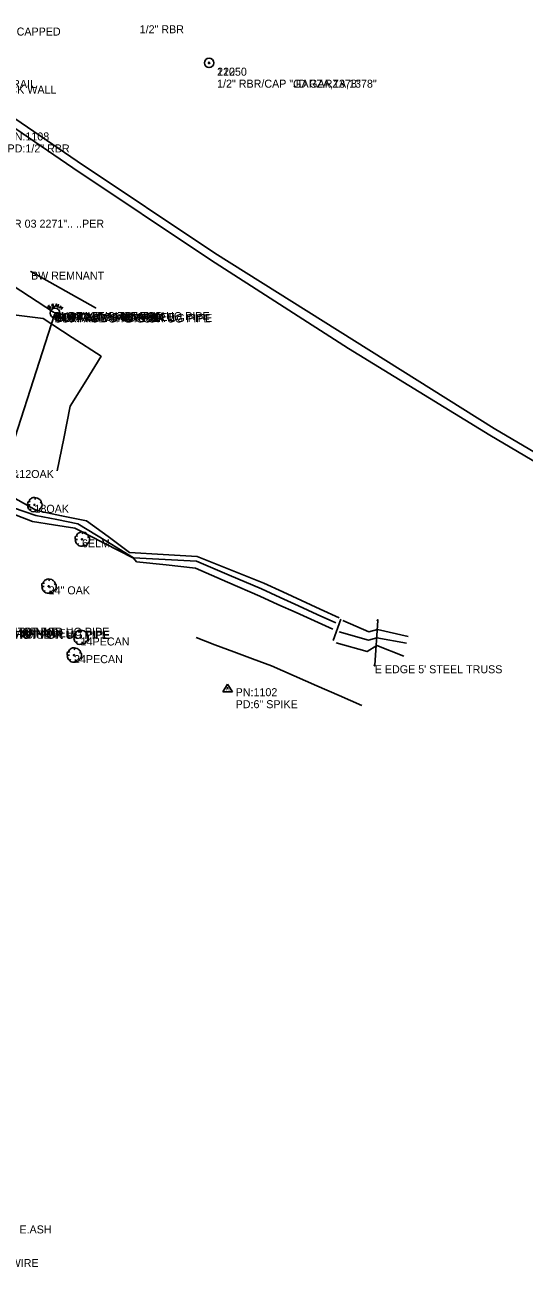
# Model space of a CAD drawing. Extents: x 997398 to 1003416, y 334596 to 337085.
# Drawn here: x 999504 to 999815, y 335282 to 336058 of the extents above; entities that cross this region are included whole.
import ezdxf

# ---------------------------------------------------------------- set-up
doc = ezdxf.new("R2010")
doc.units = 0
for name, color, linetype in [('S_BRIDGE', 7, 'Continuous'), ('S_BRIDGE_ANNOT', 7, 'Continuous'), ('S_EDGE_CONCRETE', 7, 'Continuous'), ('S_ELECTRIC_UTILITIES_ANNOT', 7, 'Continuous'), ('S_FENCE', 7, 'Continuous'), ('S_FENCE_ANNOT', 7, 'Continuous'), ('S_FIBER_OPTIC_CABLE_ANNOT', 7, 'Continuous'), ('S_GAS_UTILITIES_ANNOT', 7, 'Continuous'), ('S_GRD_PT_SYM', 7, 'Continuous'), ('S_IRON_PIN', 7, 'Continuous'), ('S_IRON_PIN_ANNOT', 7, 'Continuous'), ('S_MANHOLE_ANNOT', 7, 'Continuous'), ('S_MISC_TOPO_POINT', 7, 'Continuous'), ('S_MSC_PT_SYM', 7, 'Continuous'), ('S_RAILROAD', 7, 'Continuous'), ('S_RAILROAD_ANNOT', 7, 'Continuous'), ('S_SANITARY_SEWER', 7, 'Continuous'), ('S_SANITARY_SEWER_ANNOT', 7, 'Continuous'), ('S_SECONDARY_CTL', 7, 'Continuous'), ('S_SECONDARY_CTL_ANNOT', 7, 'Continuous'), ('S_STR_PT_SYM', 7, 'Continuous'), ('S_STREAM', 7, 'Continuous'), ('S_SURVEY_TEXT_ANNOT', 7, 'Continuous'), ('S_TREE', 7, 'Continuous'), ('S_TREE_ANNOT', 7, 'Continuous'), ('S_UTL_PT_SYM', 7, 'Continuous')]:
    doc.layers.add(name, color=color, linetype=linetype)

msp = doc.modelspace()

# ---------------------------------------------------------------- linework, layer by layer
at = {"layer": 'S_BRIDGE'}
msp.add_line((999721.99, 335657.91), (999723.92, 335685.93), dxfattribs=at)
at = {"layer": 'S_EDGE_CONCRETE'}
msp.add_lwpolyline([(999700.78, 335686.72), (999696, 335673.33)], dxfattribs=at)
at = {"layer": 'S_FENCE'}
msp.add_line((999507.42, 335903.8), (999547.73, 335881.19), dxfattribs=at)
at = {"layer": 'S_GRD_PT_SYM'}
for points in [[(999521.53, 335878.51), (999521.53, 335878.56), (999521.53, 335878.51), (999521.48, 335878.51), (999521.53, 335878.51), (999521.53, 335878.46), (999521.53, 335878.51), (999521.58, 335878.51)], [(999522.12, 335877.02), (999522.12, 335877.07), (999522.12, 335877.02), (999522.07, 335877.02), (999522.12, 335877.02), (999522.12, 335876.97), (999522.12, 335877.02), (999522.17, 335877.02)], [(999523.23, 335877.41), (999523.23, 335877.46), (999523.23, 335877.41), (999523.18, 335877.41), (999523.23, 335877.41), (999523.23, 335877.36), (999523.23, 335877.41), (999523.28, 335877.41)]]:
    msp.add_lwpolyline(points, dxfattribs=at)
at = {"layer": 'S_IRON_PIN'}
for centre, radius in [((999618.58, 336034.2), 2.91), ((999618.59, 336034.19), 2.91), ((999618.58, 336034.2), 0.411), ((999618.59, 336034.19), 0.411), ((999618.58, 336034.2), 0.262), ((999618.59, 336034.19), 0.262), ((999618.58, 336034.2), 0.212), ((999618.59, 336034.19), 0.212), ((999618.58, 336034.2), 0.145), ((999618.59, 336034.19), 0.145), ((999618.58, 336034.2), 0.0822), ((999618.59, 336034.19), 0.0822), ((999618.58, 336034.2), 0.0581), ((999618.59, 336034.19), 0.0581)]:
    msp.add_circle(centre, radius, dxfattribs=at)
at = {"layer": 'S_MSC_PT_SYM'}
for points in [[(999533.62, 335968.65), (999533.62, 335968.7), (999533.62, 335968.65), (999533.57, 335968.65), (999533.62, 335968.65), (999533.62, 335968.6), (999533.62, 335968.65), (999533.67, 335968.65)], [(999536.15, 335972.87), (999536.15, 335972.92), (999536.15, 335972.87), (999536.1, 335972.87), (999536.15, 335972.87), (999536.15, 335972.82), (999536.15, 335972.87), (999536.2, 335972.87)], [(999622.21, 335915.36), (999622.21, 335915.41), (999622.21, 335915.36), (999622.16, 335915.36), (999622.21, 335915.36), (999622.21, 335915.31), (999622.21, 335915.36), (999622.26, 335915.36)], [(999619.54, 335911.2), (999619.54, 335911.25), (999619.54, 335911.2), (999619.49, 335911.2), (999619.54, 335911.2), (999619.54, 335911.15), (999619.54, 335911.2), (999619.59, 335911.2)], [(999507.42, 335903.8), (999507.42, 335903.85), (999507.42, 335903.8), (999507.37, 335903.8), (999507.42, 335903.8), (999507.42, 335903.75), (999507.42, 335903.8), (999507.47, 335903.8)], [(999547.73, 335881.19), (999547.73, 335881.24), (999547.73, 335881.19), (999547.68, 335881.19), (999547.73, 335881.19), (999547.73, 335881.14), (999547.73, 335881.19), (999547.78, 335881.19)], [(999705.58, 335855.87), (999705.58, 335855.92), (999705.58, 335855.87), (999705.53, 335855.87), (999705.58, 335855.87), (999705.58, 335855.82), (999705.58, 335855.87), (999705.63, 335855.87)], [(999796.54, 335805.79), (999796.54, 335805.84), (999796.54, 335805.79), (999796.49, 335805.79), (999796.54, 335805.79), (999796.54, 335805.74), (999796.54, 335805.79), (999796.59, 335805.79)], [(999793.92, 335801.56), (999793.92, 335801.61), (999793.92, 335801.56), (999793.87, 335801.56), (999793.92, 335801.56), (999793.92, 335801.51), (999793.92, 335801.56), (999793.97, 335801.56)]]:
    msp.add_lwpolyline(points, dxfattribs=at)
at = {"layer": 'S_RAILROAD'}
for p, q in [((999453.35, 336023.54), (999533.62, 335968.65)), ((999536.15, 335972.87), (999456.02, 336027.69)), ((999533.62, 335968.65), (999619.54, 335911.2)), ((999622.21, 335915.36), (999536.15, 335972.87)), ((999796.54, 335805.79), (999622.21, 335915.36)), ((999619.54, 335911.2), (999705.58, 335855.87)), ((999705.58, 335855.87), (999793.92, 335801.56)), ((999889.76, 335750.52), (999796.54, 335805.79)), ((999793.92, 335801.56), (999880.36, 335750.3))]:
    msp.add_line(p, q, dxfattribs=at)
at = {"layer": 'S_SANITARY_SEWER'}
for p, q in [((999358.9, 335984.04), (999521.53, 335878.51)), ((999518.06, 335882.23), (999517.98, 335881.84)), ((999518.6, 335882.62), (999518.06, 335882.23)), ((999519.03, 335882.54), (999518.6, 335882.62)), ((999525.03, 335880.99), (999526.27, 335882.46)), ((999459, 335681.35), (999522.12, 335877.02)), ((999517.98, 335881.84), (999518.17, 335881.57)), ((999518.17, 335881.57), (999518.6, 335881.46)), ((999518.6, 335881.46), (999519.14, 335881.8)), ((999519.14, 335880.64), (999518.76, 335880.72)), ((999519.14, 335881.8), (999519.61, 335881.73)), ((999519.69, 335881.03), (999519.14, 335880.64)), ((999519.61, 335881.73), (999519.76, 335881.46)), ((999519.76, 335881.46), (999519.69, 335881.03)), ((999525.69, 335881.77), (999526.66, 335880.95)), ((999527.24, 335881.65), (999526, 335880.18))]:
    msp.add_line(p, q, dxfattribs=at)
for points in [[(999521.7, 335883.16), (999521.35, 335883.43), (999520.69, 335883.35), (999520.46, 335883.01), (999520.5, 335882.7), (999520.85, 335882.39), (999521.47, 335882.5), (999521.86, 335882.19), (999521.89, 335881.88), (999521.62, 335881.49), (999521, 335881.42), (999520.65, 335881.69)], [(999524.14, 335881.3), (999524.68, 335883.16), (999523.64, 335882.15), (999523.25, 335883.59), (999522.71, 335881.73)]]:
    msp.add_lwpolyline(points, dxfattribs=at)
msp.add_circle((999522.39, 335877.93), 3.05, dxfattribs=at)
at = {"layer": 'S_SECONDARY_CTL'}
for p, q in [((999630.16, 335646.2), (999627.15, 335641.25)), ((999630.16, 335646.2), (999633.11, 335641.25)), ((999627.15, 335641.25), (999633.11, 335641.25))]:
    msp.add_line(p, q, dxfattribs=at)
for radius in [0.311, 0.183, 0.103]:
    msp.add_circle((999630.16, 335643.59), radius, dxfattribs=at)
at = {"layer": 'S_STR_PT_SYM'}
for points in [[(999723.92, 335685.93), (999723.92, 335686.43), (999723.92, 335685.93), (999723.42, 335685.93), (999723.92, 335685.93), (999723.92, 335685.43), (999723.92, 335685.93), (999724.42, 335685.93)], [(999721.99, 335657.91), (999721.99, 335658.41), (999721.99, 335657.91), (999721.49, 335657.91), (999721.99, 335657.91), (999721.99, 335657.41), (999721.99, 335657.91), (999722.49, 335657.91)]]:
    msp.add_lwpolyline(points, dxfattribs=at)
at = {"layer": 'S_STREAM'}
for points in [[(999331.89, 335832.2), (999349.69, 335826.31), (999367.5, 335820.43), (999381.08, 335812.09), (999394.65, 335803.75), (999408.23, 335795.41), (999421.81, 335787.07), (999434.28, 335784.52), (999446.75, 335781.96), (999459.22, 335779.4), (999471.69, 335776.85), (999491.33, 335765.68), (999510.96, 335754.51)], [(999325.68, 335825.18), (999344.61, 335818.97), (999363.54, 335812.75), (999377.19, 335804.59), (999390.85, 335796.43), (999404.51, 335788.27), (999418.17, 335780.11), (999430.58, 335776.57), (999442.99, 335773.03), (999455.4, 335769.5), (999467.81, 335765.96), (999489.15, 335758.72), (999510.5, 335751.47)], [(999363.15, 335804.23), (999376.49, 335797.55), (999389.84, 335790.87), (999403.19, 335784.2), (999416.53, 335777.52), (999429.2, 335774.06), (999441.86, 335770.61), (999454.53, 335767.16), (999467.19, 335763.7), (999487.73, 335755.71), (999508.28, 335747.72)], [(999536.66, 335746.34), (999523.58, 335748.9), (999510.5, 335751.47)], [(999542.06, 335748.18), (999526.51, 335751.35), (999510.96, 335754.51)], [(999534.79, 335743.58), (999521.53, 335745.65), (999508.28, 335747.72)], [(999534.79, 335743.58), (999553.06, 335734.21), (999571.33, 335724.84), (999573.38, 335722.52), (999591.76, 335720.55), (999610.14, 335718.57), (999630.16, 335709.81), (999650.18, 335701.05), (999661.59, 335695.93), (999673.01, 335690.8), (999684.42, 335685.68), (999695.83, 335680.55)], [(999536.66, 335746.34), (999554.05, 335735.71), (999571.44, 335725.08), (999591.1, 335724), (999610.75, 335722.92), (999631.03, 335714.27), (999651.31, 335705.63), (999662.9, 335700.31), (999674.49, 335694.99), (999686.08, 335689.67), (999697.67, 335684.36)], [(999542.06, 335748.18), (999555.52, 335738.26), (999568.99, 335728.33), (999590.03, 335727.04), (999611.07, 335725.75), (999631.94, 335717.5), (999652.81, 335709.25), (999664.54, 335703.84), (999676.27, 335698.44), (999688, 335693.04), (999699.73, 335687.63)], [(999702.16, 335685.83), (999718.26, 335678.85), (999723.63, 335680.16), (999742.83, 335675.94)], [(999699.85, 335678.75), (999718.18, 335673.65), (999723.29, 335675.02), (999741.74, 335671.61)], [(999698.02, 335671.95), (999717.24, 335666.5), (999723.34, 335670.2), (999740.2, 335663.52)]]:
    msp.add_lwpolyline(points, dxfattribs=at)
at = {"layer": 'S_TREE'}
for p, q in [((999505.7, 335758.05), (999506.82, 335758.05)), ((999506.36, 335760.37), (999506.86, 335759.79)), ((999510.16, 335762.39), (999509.77, 335761.53)), ((999513.72, 335759.6), (999513.06, 335759.32)), ((999506.86, 335754.87), (999507.33, 335755.57)), ((999510.54, 335754.6), (999510.47, 335755.37)), ((999512.95, 335755.49), (999512.48, 335755.91)), ((999535.36, 335736.5), (999536.48, 335736.5)), ((999536.02, 335738.82), (999536.52, 335738.24)), ((999539.82, 335740.84), (999539.43, 335739.99)), ((999543.38, 335738.05), (999542.72, 335737.78)), ((999536.52, 335733.32), (999536.99, 335734.02)), ((999540.2, 335733.05), (999540.13, 335733.83)), ((999542.61, 335733.94), (999542.14, 335734.37)), ((999519.02, 335711.47), (999518.63, 335710.62)), ((999514.57, 335707.13), (999515.69, 335707.13)), ((999515.22, 335709.46), (999515.73, 335708.87)), ((999515.73, 335703.95), (999516.19, 335704.65)), ((999519.41, 335703.68), (999519.33, 335704.46)), ((999521.81, 335704.57), (999521.35, 335705)), ((999522.59, 335708.68), (999521.93, 335708.41)), ((999534.54, 335675.16), (999535.67, 335675.16)), ((999535.2, 335677.49), (999535.7, 335676.91)), ((999535.7, 335671.99), (999536.17, 335672.68)), ((999539, 335679.5), (999538.61, 335678.65)), ((999541.79, 335672.61), (999541.32, 335673.03)), ((999542.56, 335676.71), (999541.9, 335676.44)), ((999531.03, 335666.45), (999531.53, 335665.87)), ((999534.83, 335668.46), (999534.44, 335667.61)), ((999538.39, 335665.67), (999537.73, 335665.4)), ((999539.39, 335671.72), (999539.31, 335672.49)), ((999530.37, 335664.12), (999531.49, 335664.12)), ((999531.53, 335660.95), (999532, 335661.64)), ((999535.21, 335660.67), (999535.14, 335661.45)), ((999537.62, 335661.57), (999537.15, 335661.99))]:
    msp.add_line(p, q, dxfattribs=at)
for points in [[(999523.83, 335779.4), (999527.91, 335799.55), (999531.98, 335819.7), (999541.56, 335835.34), (999551.14, 335850.97), (999533.12, 335862.72), (999515.1, 335874.46), (999491.75, 335877.42), (999480.27, 335894.95), (999468.8, 335912.48), (999454.65, 335914.32), (999440.5, 335916.16)], [(999714.01, 335632.69), (999699.88, 335638.92), (999685.75, 335645.16), (999671.62, 335651.39), (999657.49, 335657.62), (999645.75, 335662), (999634.01, 335666.39), (999622.27, 335670.77), (999610.53, 335675.15)]]:
    msp.add_lwpolyline(points, dxfattribs=at)
for centre in [(999509.6, 335758.14), (999539.26, 335736.59), (999518.46, 335707.23), (999538.44, 335675.26), (999534.27, 335664.22)]:
    msp.add_circle(centre, 0.341, dxfattribs=at)
for centre, major_axis, ratio, start_param, end_param in [((999506.03, 335759.23), (0.31, 1.03), 0.646762, 0, 3.141593), ((999506.33, 335756.58), (-0.61, 1.6), 0.420543, 6.283185, 9.424777), ((999508.26, 335761.34), (1.86, 1.08), 0.471018, 0, 3.141593), ((999511.92, 335761.02), (-1.81, 1.36), 0.405113, 3.141593, 6.283186), ((999513.27, 335757.61), (0.46, 2.04), 0.482994, 3.141593, 6.283185), ((999508.79, 335754.8), (-1.83, 0.19), 0.529943, 0, 3.141593), ((999511.75, 335755.09), (1.09, 0.46), 0.711534, 3.141592, 6.283185), ((999535.69, 335737.68), (0.31, 1.03), 0.646762, 0, 3.141593), ((999535.99, 335735.03), (-0.61, 1.6), 0.420543, 6.283185, 9.424777), ((999537.92, 335739.8), (1.86, 1.08), 0.471018, 0, 3.141593), ((999541.58, 335739.47), (-1.81, 1.36), 0.405113, 3.141593, 6.283186), ((999542.93, 335736.06), (0.46, 2.04), 0.482994, 3.141593, 6.283185), ((999538.45, 335733.25), (-1.83, 0.19), 0.529943, 0, 3.141593), ((999541.41, 335733.54), (1.09, 0.46), 0.711534, 3.141592, 6.283185), ((999517.13, 335710.43), (1.86, 1.08), 0.471018, 0, 3.141593), ((999520.78, 335710.1), (-1.81, 1.36), 0.405113, 3.141593, 6.283186), ((999514.89, 335708.31), (0.31, 1.03), 0.646762, 0, 3.141593), ((999515.2, 335705.66), (-0.61, 1.6), 0.420543, 6.283185, 9.424777), ((999517.66, 335703.88), (-1.83, 0.19), 0.529943, 0, 3.141593), ((999520.62, 335704.17), (1.09, 0.46), 0.711534, 3.141592, 6.283185), ((999522.14, 335706.7), (0.46, 2.04), 0.482994, 3.141593, 6.283185), ((999534.87, 335676.35), (0.31, 1.03), 0.646762, 0, 3.141593), ((999535.17, 335673.7), (-0.61, 1.6), 0.420543, 6.283185, 9.424777), ((999537.1, 335678.46), (1.86, 1.08), 0.471018, 0, 3.141593), ((999540.76, 335678.14), (-1.81, 1.36), 0.405113, 3.141593, 6.283186), ((999540.59, 335672.21), (1.09, 0.46), 0.711534, 3.141592, 6.283185), ((999542.11, 335674.73), (0.46, 2.04), 0.482994, 3.141593, 6.283185), ((999530.7, 335665.31), (0.31, 1.03), 0.646762, 0, 3.141593), ((999532.93, 335667.42), (1.86, 1.08), 0.471018, 0, 3.141593), ((999536.59, 335667.1), (-1.81, 1.36), 0.405113, 3.141593, 6.283186), ((999537.64, 335671.92), (-1.83, 0.19), 0.529943, 0, 3.141593), ((999537.94, 335663.69), (0.46, 2.04), 0.482994, 3.141593, 6.283185), ((999531, 335662.66), (-0.61, 1.6), 0.420543, 6.283185, 9.424777), ((999533.46, 335660.87), (-1.83, 0.19), 0.529943, 0, 3.141593), ((999536.42, 335661.17), (1.09, 0.46), 0.711534, 3.141592, 6.283185)]:
    msp.add_ellipse(centre, major_axis=major_axis, ratio=ratio, start_param=start_param, end_param=end_param, dxfattribs=at)
at = {"layer": 'S_UTL_PT_SYM'}
for points in [[(999521.53, 335878.51), (999521.53, 335878.56), (999521.53, 335878.51), (999521.48, 335878.51), (999521.53, 335878.51), (999521.53, 335878.46), (999521.53, 335878.51), (999521.58, 335878.51)], [(999522.12, 335877.02), (999522.12, 335877.07), (999522.12, 335877.02), (999522.07, 335877.02), (999522.12, 335877.02), (999522.12, 335876.97), (999522.12, 335877.02), (999522.17, 335877.02)], [(999522.39, 335877.93), (999522.39, 335877.98), (999522.39, 335877.93), (999522.34, 335877.93), (999522.39, 335877.93), (999522.39, 335877.88), (999522.39, 335877.93), (999522.44, 335877.93)], [(999523.23, 335877.41), (999523.23, 335877.46), (999523.23, 335877.41), (999523.18, 335877.41), (999523.23, 335877.41), (999523.23, 335877.36), (999523.23, 335877.41), (999523.28, 335877.41)]]:
    msp.add_lwpolyline(points, dxfattribs=at)

# ---------------------------------------------------------------- texts
at = {"layer": 'S_BRIDGE_ANNOT'}
for s, p in [('INSIDE 16"DECK WALL', (999450.75, 336015)), ("E EDGE 5' STEEL TRUSS", (999721.99, 335652.91))]:
    msp.add_text(s, height=5, dxfattribs=at).set_placement(p)
at = {"layer": 'S_ELECTRIC_UTILITIES_ANNOT'}
msp.add_text('LOWEST WIRE', height=5, dxfattribs=at).set_placement((999464.65, 335282.01))
at = {"layer": 'S_FENCE_ANNOT'}
msp.add_text('BW REMNANT', height=5, dxfattribs=at).set_placement((999507.42, 335898.8))
at = {"layer": 'S_FIBER_OPTIC_CABLE_ANNOT'}
msp.add_text('SN,SPRINT,"AR 03 2271".. ..PER ', height=5, dxfattribs=at).set_placement((999452.42, 335931.25))
at = {"layer": 'S_GAS_UTILITIES_ANNOT'}
msp.add_text('AT SN,MARKED AS CAPPED', height=5, dxfattribs=at).set_placement((999435.67, 336051.26))
at = {"layer": 'S_IRON_PIN_ANNOT'}
for s, p in [('1/2" RBR', (999575.26, 336052.68)), ('210', (999623.58, 336026.2)), ('12250', (999623.59, 336026.19)), ('1/2" RBR/CAP "JD GARZA,1378"', (999623.58, 336018.7)), ('1/2" RBR/CAP "GARZA,1378"', (999623.59, 336018.69))]:
    msp.add_text(s, height=5, dxfattribs=at).set_placement(p)
at = {"layer": 'S_MANHOLE_ANNOT'}
for p in [(999522.39, 335872.93), (999458.9, 335675.39)]:
    msp.add_text('BOTTOM OF MANHOLE', height=5, dxfattribs=at).set_placement(p)
at = {"layer": 'S_MISC_TOPO_POINT'}
for p in [(999521.53, 335873.51), (999522.12, 335872.02), (999523.23, 335872.41), (999459, 335676.35), (999458.79, 335674.4), (999459.5, 335674.55)]:
    msp.add_text('SURFACE SHOT FOR UG PIPE', height=5, dxfattribs=at).set_placement(p)
at = {"layer": 'S_RAILROAD_ANNOT'}
msp.add_text('TOP CTR OF RAIL', height=5, dxfattribs=at).set_placement((999453.35, 336018.54))
at = {"layer": 'S_SANITARY_SEWER_ANNOT'}
for s, p in [('DI:8 TY:PVC TO WNW', (999521.53, 335873.51)), ('TOP CL OF MANHOLE', (999522.39, 335872.93)), ('DI:6 TY:PVC TO SSW', (999522.12, 335872.02)), ('DI:8 TY:PVC TO ESE', (999523.23, 335872.41)), ('TOP CL OF MANHOLE', (999458.9, 335675.39)), ('DI:6 TY:PVC TO NNE', (999459, 335676.35)), ('DI:6 TY:PVC TO SE', (999459.5, 335674.55))]:
    msp.add_text(s, height=5, dxfattribs=at).set_placement(p)
at = {"layer": 'S_SECONDARY_CTL'}
msp.add_text('TV', height=1.5, rotation=360, dxfattribs=at).set_placement((999628.96, 335641.58))
at = {"layer": 'S_SECONDARY_CTL_ANNOT'}
for s, p in [('PN:1108', (999492.79, 335985.74)), ('PD:1/2" RBR', (999492.79, 335978.24)), ('PN:1102', (999635.16, 335638.59)), ('PD:6" SPIKE', (999635.16, 335631.09))]:
    msp.add_text(s, height=5, dxfattribs=at).set_placement(p)
at = {"layer": 'S_SURVEY_TEXT_ANNOT'}
msp.add_text('RESIDENCE, 40 E.ASH', height=5, dxfattribs=at).set_placement((999448.19, 335303))
at = {"layer": 'S_TREE_ANNOT'}
for s, p in [('TWIN 18&12OAK', (999469.29, 335774.88)), ('18OAK', (999509.6, 335753.14)), ('6ELM', (999539.26, 335731.59)), ('24" OAK', (999518.46, 335702.23)), ('14PECAN', (999538.44, 335670.26)), ('24PECAN', (999534.27, 335659.22))]:
    msp.add_text(s, height=5, dxfattribs=at).set_placement(p)

doc.saveas('drawing.dxf')
